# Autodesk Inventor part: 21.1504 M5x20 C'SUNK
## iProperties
Created: 2006-12
Part Number: 21.1504 M5x20 C'SUNK
Material: Steel, Mild
Description: Hexagon socket countersunk head cap screws
Document SubType Name: Modeling
Standard: DIN 7991
Designer: Andy Moles
Standards Organization: DIN
Language: en-US
Size Designation: M5x20
Categories: <MemberInstance Version="R10.0.0"><Categories><Category DisplayName="Fasteners" InternalName="e4da775c-781d-43d5-af7c-5136215cf5a6" Mnemonic="FSTN"><Category Di
Density: 7.86 g/cm^3
Author: Andy Moles
Revision Number: 1
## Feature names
1. Revolution1
2. Extrusion1
3. Fillet1
4. Chamfer1
